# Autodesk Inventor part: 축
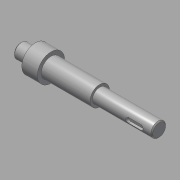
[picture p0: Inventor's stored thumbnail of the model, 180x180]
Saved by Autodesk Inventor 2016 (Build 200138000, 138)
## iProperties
Created: 2015-09
Part Number: 축
Material: 강철, 연강
Document SubType Name: Modeling
Designer: mduedu
Density: 7.86 g/cm^3
Mass: 263.424 g
Surface Area: 86.4309 cm^2
Volume: 33.5145 cm^3
Appearance: 강철
Author: mduedu
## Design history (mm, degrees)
sketch "스케치1"
  geometry: L1 (-71, 0)-(71, 0); L2 (-71, 0)-(-71, 7.5); L3 (-71, 7.5)-(-56, 7.5); L4 (-56, 7.5)-(-56, 14); L5 (-56, 14)-(-40, 14); L6 (-40, 14)-(-40, 10); L7 (-40, 10)-(10, 10); L8 (10, 10)-(10, 7.5); L9 (10, 7.5)-(71, 7.5); L10 (71, 7.5)-(71, 0); 2 further points
  constraints: 20 end point, 5 parallel, 2 horizontal, 2 perpendicular, 1 coincident, 1 midpoint, 1 vertical
  dimensions: "d0" = 142 distance of L1.start L1.end; "d2" = 16 distance of L4.end L5.end; "d3" = 50 distance of L6.end L7.end; "d5" = 15 diameter of L3 L1; "d6" = 15 diameter of L9 L1; "d7" = 20 diameter of L7 L1; "d8" = 28 diameter of L5 L1; "d31" = 15 distance of L2.end L3.end
revolve "회전1" sketch "스케치1" stored, may be unused: angle "d9" = 90 deg
node "작업 평면1"
sketch "스케치2"
  geometry: L1 (6, 2.5)-(19, 2.5); L2 (19, -2.5)-(6, -2.5); L3 (6, 2.5)-(19, -2.5); L4 (19, 2.5)-(6, -2.5); L5 (30.5, -7.5)-(30.5, 7.5) reference; A1 r 2.5 centre (6, 0) between (6, 2.5) and (6, -2.5); A2 r 2.5 centre (19, 0) between (19, -2.5) and (19, 2.5); 2 further points
  constraints: 8 end point, 4 point on circle, 4 tangent, 2 centre point, 2 midpoint, 1 horizontal, 1 horizontal alignment, 1 parallel
  dimensions: "d10" = 18 dimension on A2 A1; "d12" = 9 distance edge to line of A2 L5; "d13" = 5 distance between parallel lines of L2 L1
extrude "돌출1" cut sketch "스케치2" distance "d14" = 3; taper "d15" = 0 deg
node "작업 평면2"
sketch "스케치4"
  geometry: L1 (3, -3)-(-13, -3); L2 (-13, 3)-(3, 3); L3 (-25, 10)-(-25, -10) reference; A1 r 3 centre (-13, 0) between (-13, 3) and (-13, -3); A2 r 3 centre (3, 0) between (3, -3) and (3, 3); 1 further point
  constraints: 4 end point, 4 point on circle, 4 tangent, 2 centre point, 1 horizontal, 1 horizontal alignment, 1 parallel
  dimensions: "d16" = 22 dimension on A1 A2; "d18" = 6 distance between parallel lines of L2 L1; "d19" = 9 distance edge to line of A1 L3
extrude "돌출2" cut sketch "스케치4" distance "d20" = 3.5; taper "d21" = 0 deg
sketch "스케치5"
  geometry: L1 (10, 7.5)-(71, 7.5) reference; L2 (10, -7.5)-(71, -7.5) reference; L3 (45, 7.5)-(45, -7.5); L4 (45, -5.5)-(43, -7.5); L5 (45, -7.5)-(43, -7.5); L6 (45, -7.5)-(45, -5.5); L7 (10, -10)-(10, 10) reference; 1 further point
  constraints: 8 end point, 4 point on line, 1 collinear, 1 perpendicular
  dimensions: "d22" = 4 diameter of L4.end L3; "d24" = 45 deg angle of L3 L4; "d26" = 35 distance between parallel lines of L3 L7
revolve "회전2" sketch "스케치5" stored, may be unused: angle "d27" = 90 deg
chamfer "모따기1" distance "d28" = 1; stored, may be unused: second distance "d29" = 2, angle "d30" = 45 deg
sketch "스케치6"
  geometry: L1 (45, -5.5)-(43, -7.5) reference; L2 (45, -5.5)-(47, -7.5) reference; 2 further points
  constraints: 1 coincident
node "솔리드1"
